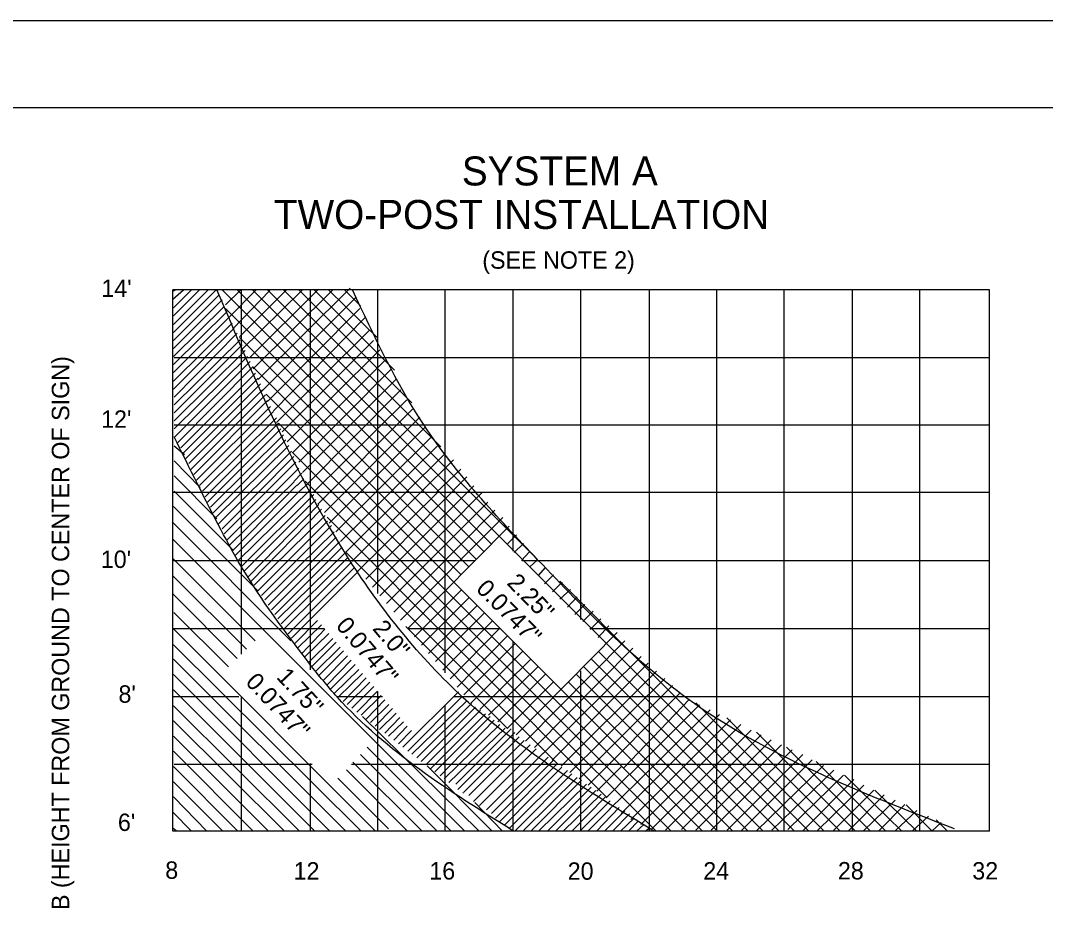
# Model space of a CAD drawing. Extents: x 644358 to 648627, y 294594 to 295782.
# Drawn here: x 645566.7 to 645743.5, y 295627.9 to 295781.6 of the extents above; entities that cross this region are included whole.
import ezdxf

# ---------------------------------------------------------------- set-up
doc = ezdxf.new("R2010")
doc.units = 0
for name, color, linetype in [('1', 7, 'Continuous'), ('10', 7, 'Continuous'), ('2', 7, 'Continuous'), ('4', 7, 'Continuous'), ('PLT-BNDY', 7, 'Continuous')]:
    doc.layers.add(name, color=color, linetype=linetype)

msp = doc.modelspace()

# ---------------------------------------------------------------- linework, layer by layer
at = {"layer": '1'}
msp.add_line((645239.31, 295766.63), (646025.31, 295766.63), dxfattribs=at)
at = {"layer": '10'}
for p, q in [((645606.19, 295723.43), (645618.06, 295735.31)), ((645607.69, 295719.68), (645623.56, 295735.43)), ((645592.94, 295734.93), (645593.44, 295735.18)), ((645592.94, 295733.56), (645594.81, 295735.18)), ((645593.06, 295732.06), (645596.19, 295735.18)), ((645593.06, 295730.68), (645597.56, 295735.18)), ((645593.06, 295729.18), (645599.06, 295735.18)), ((645593.06, 295727.81), (645600.44, 295735.18)), ((645593.06, 295726.43), (645600.94, 295734.31)), ((645646.62, 295690), (645601.44, 295735.18)), ((645602.06, 295732.56), (645604.69, 295735.18)), ((645602.69, 295730.43), (645607.31, 295735.18)), ((645603.31, 295728.43), (645609.69, 295735.06)), ((645647.92, 295691.32), (645604.06, 295735.18)), ((645604.44, 295727.06), (645612.56, 295735.18)), ((645604.69, 295724.68), (645615.31, 295735.18)), ((645650.65, 295691.28), (645606.69, 295735.18)), ((645606.81, 295721.56), (645620.56, 295735.18)), ((645608.19, 295717.56), (645624.44, 295733.81)), ((645655.79, 295688.71), (645609.31, 295735.18)), ((645639.19, 295708.06), (645612.06, 295735.18)), ((645634.19, 295715.68), (645614.69, 295735.18)), ((645631.19, 295721.31), (645617.31, 295735.18)), ((645628.31, 295726.81), (645619.81, 295735.18)), ((645625.31, 295732.43), (645622.56, 295735.18)), ((645593.06, 295725.06), (645601.44, 295733.43)), ((645593.06, 295723.68), (645601.81, 295732.31)), ((645645.31, 295688.68), (645602.06, 295731.93)), ((645609.31, 295715.93), (645625.19, 295731.93)), ((645593.06, 295722.31), (645602.31, 295731.43)), ((645593.06, 295720.93), (645602.81, 295730.56)), ((645610.31, 295714.31), (645626.06, 295730.31)), ((645593.06, 295719.43), (645603.19, 295729.43)), ((645593.06, 295718.06), (645603.56, 295728.56)), ((645593.19, 295716.68), (645604.06, 295727.68)), ((645593.19, 295715.31), (645604.56, 295726.56)), ((645644.01, 295687.37), (645604.44, 295726.93)), ((645610.81, 295712.31), (645626.81, 295728.18)), ((645593.19, 295713.93), (645604.94, 295725.68)), ((645611.81, 295710.68), (645627.56, 295726.43)), ((645612.69, 295708.93), (645628.69, 295724.81)), ((645593.19, 295712.56), (645605.44, 295724.68)), ((645593.19, 295711.18), (645605.81, 295723.68)), ((645613.69, 295707.18), (645629.56, 295723.06)), ((645593.19, 295709.68), (645606.31, 295722.81)), ((645593.81, 295708.81), (645606.69, 295721.81)), ((645642.67, 295686.01), (645606.69, 295721.93)), ((645614.69, 295705.43), (645630.56, 295721.43)), ((645594.31, 295707.93), (645607.19, 295720.81)), ((645594.69, 295706.93), (645607.69, 295719.93)), ((645615.31, 295703.68), (645631.44, 295719.68)), ((645595.19, 295706.06), (645608.06, 295718.93)), ((645595.69, 295705.18), (645608.44, 295717.93)), ((645615.81, 295701.31), (645632.31, 295717.93)), ((645596.06, 295704.18), (645608.94, 295717.06)), ((645596.56, 295703.31), (645609.31, 295716.06)), ((645672.23, 295653.91), (645609.06, 295717.18)), ((645617.19, 295700.18), (645633.31, 295716.18)), ((645597.06, 295702.31), (645609.81, 295715.06)), ((645597.56, 295701.43), (645610.31, 295714.18)), ((645617.94, 295698.18), (645634.31, 295714.56)), ((645598.06, 295700.43), (645610.81, 295713.06)), ((645619.11, 295696.74), (645635.56, 295713.18)), ((645598.56, 295699.43), (645611.19, 295712.18)), ((645598.94, 295698.56), (645611.56, 295711.18)), ((645681.56, 295641.81), (645611.19, 295712.18)), ((645619.94, 295694.94), (645636.44, 295711.43)), ((645599.44, 295697.68), (645612.06, 295710.18)), ((645599.94, 295696.68), (645612.44, 295709.31)), ((645621.07, 295693.44), (645637.56, 295709.81)), ((645594.94, 295706.68), (645593.19, 295708.18)), ((645600.31, 295695.81), (645612.94, 295708.31)), ((645600.81, 295694.81), (645613.44, 295707.31)), ((645678.94, 295641.81), (645613.56, 295707.18)), ((645621.87, 295691.74), (645638.56, 295708.18)), ((645597.69, 295701.06), (645593.19, 295705.68)), ((645601.44, 295693.93), (645613.81, 295706.43)), ((645601.81, 295693.06), (645614.19, 295705.43)), ((645633.14, 295700.18), (645639.69, 295706.68)), ((645635.69, 295700.18), (645641.35, 295705.84)), ((645602.31, 295692.06), (645614.69, 295704.43)), ((645613.81, 295702.1), (645615.19, 295703.56)), ((645638.36, 295700.18), (645642.63, 295704.23)), ((645600.56, 295695.68), (645593.19, 295703.06)), ((645602.81, 295691.18), (645613.87, 295702.02)), ((645614.4, 295701.4), (645615.56, 295702.56)), ((645676.31, 295641.81), (645615.81, 295702.18)), ((645626.23, 295685.23), (645643.69, 295702.88)), ((645603.44, 295690.18), (645593.19, 295700.43)), ((645603.31, 295690.18), (645614.35, 295701.46)), ((645603.69, 295689.31), (645615.03, 295700.65)), ((645604.19, 295688.43), (645616.7, 295700.7)), ((645615.06, 295700.62), (645616.06, 295701.56)), ((645622.81, 295689.93), (645633.14, 295700.18)), ((645623.81, 295688.31), (645635.69, 295700.18)), ((645624.81, 295686.56), (645638.59, 295700.18)), ((645627.38, 295683.87), (645644.88, 295701.38)), ((645628.64, 295682.39), (645646.24, 295700.17)), ((645604.81, 295687.43), (645617.26, 295699.88)), ((645605.31, 295686.68), (645617.64, 295699.01)), ((645629.79, 295681.04), (645647.29, 295698.53)), ((645607.67, 295683.2), (645593.06, 295697.81)), ((645605.94, 295685.68), (645618.16, 295698.15)), ((645606.44, 295684.93), (645618.59, 295697.34)), ((645631.05, 295679.55), (645648.5, 295697.18)), ((645613.33, 295674.62), (645592.84, 295695.12)), ((645606.98, 295684.23), (645619.23, 295696.22)), ((645607.65, 295683.28), (645619.63, 295695.25)), ((645667.75, 295647.63), (645619.57, 295695.93)), ((645632.2, 295678.2), (645649.87, 295695.87)), ((645608.27, 295682.45), (645620.35, 295694.53)), ((645608.82, 295681.69), (645620.79, 295693.4)), ((645633.46, 295676.71), (645650.98, 295694.41)), ((645650.65, 295691.28), (645652.26, 295692.88)), ((645643.22, 295641.88), (645592.91, 295692.19)), ((645609.41, 295680.78), (645621.15, 295692.52)), ((645609.98, 295679.98), (645621.73, 295691.72)), ((645700.19, 295641.81), (645650.65, 295691.28)), ((645651.85, 295689.84), (645653.44, 295691.43)), ((645610.53, 295679.15), (645622.15, 295690.77)), ((645611.06, 295678.43), (645622.59, 295689.71)), ((645659.44, 295653.31), (645622.81, 295689.93)), ((645653.11, 295688.49), (645654.44, 295689.93)), ((645607.18, 295674.62), (645592.91, 295688.9)), ((645611.67, 295677.54), (645623.08, 295688.95)), ((645612.24, 295676.73), (645623.75, 295688.2)), ((645654.54, 295687.39), (645655.81, 295688.56)), ((645605.65, 295673.16), (645592.91, 295685.9)), ((645612.83, 295675.83), (645624.29, 295687.29)), ((645613.43, 295675.06), (645624.95, 295686.55)), ((645656.02, 295685.91), (645657.31, 295687.31)), ((645657.06, 295684.43), (645658.61, 295685.98)), ((645658.44, 295683.06), (645660.1, 295684.73)), ((645702.69, 295641.81), (645659.69, 295684.93)), ((645604.08, 295671.59), (645592.99, 295682.68)), ((645634.67, 295675.29), (645642.78, 295683.41)), ((645659.69, 295681.81), (645661.53, 295683.48)), ((645635.87, 295673.87), (645644.1, 295682.09)), ((645637.08, 295672.45), (645645.45, 295680.74)), ((645661.06, 295680.43), (645662.7, 295682.23)), ((645662.31, 295679.18), (645664, 295680.88)), ((645602.54, 295670.13), (645593.14, 295679.53)), ((645638.28, 295671.03), (645646.72, 295679.47)), ((645663.69, 295677.93), (645665.46, 295679.71)), ((645614.02, 295674.14), (645617.91, 295678.13)), ((645614.54, 295673.41), (645618.58, 295677.35)), ((645650.66, 295659.49), (645633.15, 295677.07)), ((645639.54, 295669.54), (645648.09, 295678.09)), ((645664.94, 295676.56), (645666.8, 295678.42)), ((645666.31, 295675.18), (645668.16, 295677.21)), ((645627.94, 295641.81), (645593.06, 295676.68)), ((645615.24, 295672.49), (645619.18, 295676.64)), ((645615.71, 295671.83), (645619.84, 295675.86)), ((645640.81, 295668.06), (645649.38, 295676.8)), ((645642.01, 295666.64), (645650.69, 295675.49)), ((645652.17, 295658.43), (645669.61, 295676.04)), ((645625.44, 295641.81), (645593.06, 295673.93)), ((645616.38, 295670.88), (645620.54, 295675.04)), ((645616.92, 295670.17), (645621.11, 295674.36)), ((645617.61, 295669.36), (645621.8, 295673.55)), ((645643.16, 295665.28), (645652.03, 295674.15)), ((645653.79, 295657.3), (645670.95, 295674.63)), ((645618.17, 295668.67), (645622.37, 295672.87)), ((645618.91, 295667.78), (645623.07, 295672.05)), ((645644.37, 295663.86), (645653.34, 295672.84)), ((645655.33, 295656.22), (645672.3, 295673.35)), ((645656.82, 295655.18), (645673.75, 295671.93)), ((645697.56, 295641.81), (645666.37, 295672.76)), ((645622.81, 295641.81), (645593.06, 295671.43)), ((645619.55, 295667.04), (645623.7, 295671.31)), ((645620.16, 295666.29), (645624.38, 295670.51)), ((645645.93, 295662.8), (645654.69, 295671.48)), ((645647.4, 295661.77), (645655.98, 295670.19)), ((645658.42, 295654.06), (645674.98, 295670.79)), ((645692.19, 295641.81), (645663.81, 295670.18)), ((645694.81, 295641.81), (645665.12, 295671.5)), ((645620.06, 295641.81), (645593.06, 295668.81)), ((645620.79, 295665.54), (645625.06, 295669.7)), ((645621.56, 295664.93), (645625.69, 295668.96)), ((645622.31, 295664.18), (645626.33, 295668.21)), ((645649.02, 295660.64), (645657.27, 295668.89)), ((645659.97, 295652.97), (645676.41, 295669.41)), ((645661.43, 295651.92), (645677.82, 295668.13)), ((645689.56, 295641.81), (645662.51, 295668.86)), ((645623.01, 295663.63), (645626.96, 295667.48)), ((645623.86, 295662.98), (645627.6, 295666.72)), ((645650.63, 295659.51), (645658.58, 295667.46)), ((645686.94, 295641.81), (645661.18, 295667.53)), ((645663.04, 295650.79), (645679.15, 295666.9)), ((645617.44, 295641.81), (645593.06, 295666.18)), ((645624.71, 295662.34), (645628.24, 295665.96)), ((645625.43, 295661.78), (645628.91, 295665.18)), ((645632.64, 295656.26), (645642.22, 295665.84)), ((645633.49, 295655.61), (645642.78, 295664.9)), ((645664.59, 295649.71), (645680.5, 295665.62)), ((645614.81, 295641.81), (645593.06, 295663.43)), ((645626.32, 295661.1), (645629.52, 295664.46)), ((645627.06, 295660.53), (645630.22, 295663.63)), ((645627.88, 295659.9), (645630.83, 295662.92)), ((645634.21, 295655.05), (645643.62, 295664.21)), ((645635.04, 295654.42), (645644.45, 295663.83)), ((645635.82, 295653.82), (645645.18, 295663.18)), ((645670.72, 295652.65), (645682.06, 295664.56)), ((645671.81, 295651.56), (645683.83, 295663.57)), ((645705.31, 295641.81), (645683.19, 295663.93)), ((645645.81, 295641.81), (645625.69, 295661.59)), ((645628.62, 295659.34), (645631.49, 295662.14)), ((645629.5, 295658.67), (645632.11, 295661.41)), ((645636.6, 295653.22), (645646.05, 295662.68)), ((645637.45, 295652.57), (645646.88, 295662)), ((645638.16, 295652.03), (645647.69, 295661.56)), ((645673.09, 295650.28), (645685.66, 295662.7)), ((645674.42, 295648.95), (645687.28, 295661.91)), ((645708.06, 295641.81), (645688.55, 295661.32)), ((645612.19, 295641.81), (645593.06, 295660.81)), ((645630.17, 295658.15), (645632.75, 295660.65)), ((645631.05, 295657.48), (645633.37, 295659.92)), ((645639.06, 295651.34), (645648.37, 295660.93)), ((645639.74, 295650.82), (645649.36, 295660.16)), ((645640.59, 295650.17), (645650.26, 295659.55)), ((645641.77, 295649.88), (645651.32, 295659.42)), ((645671.94, 295643.81), (645689.13, 295661)), ((645673.69, 295642.93), (645690.94, 295660.18)), ((645609.44, 295641.81), (645593.06, 295658.18)), ((645631.86, 295656.86), (645634.15, 295659.15)), ((645642.41, 295649.24), (645651.95, 295658.78)), ((645643.14, 295648.51), (645652.68, 295658.05)), ((645675.56, 295642.18), (645692.74, 295659.22)), ((645677.94, 295641.93), (645694.43, 295658.43)), ((645680.69, 295642.06), (645696.17, 295657.55)), ((645710.69, 295641.81), (645693.62, 295658.88)), ((645640.86, 295641.88), (645626.46, 295656.29)), ((645644.04, 295647.92), (645653.56, 295657.43)), ((645644.82, 295646.89), (645654.58, 295656.65)), ((645645.85, 295646.21), (645655.62, 295655.98)), ((645683.19, 295641.93), (645697.95, 295656.7)), ((645685.81, 295641.93), (645699.82, 295655.8)), ((645713.31, 295641.81), (645698.82, 295656.3)), ((645606.81, 295641.81), (645593.06, 295655.56)), ((645638.41, 295641.88), (645625.31, 295654.99)), ((645647.05, 295645.48), (645656.82, 295655.25)), ((645647.93, 295644.81), (645657.7, 295654.57)), ((645684.31, 295641.81), (645671.85, 295654.3)), ((645688.56, 295641.93), (645701.62, 295654.99)), ((645690.94, 295641.81), (645703.24, 295654.11)), ((645604.19, 295641.81), (645593.06, 295652.93)), ((645633.46, 295641.81), (645622.91, 295652.36)), ((645635.94, 295641.81), (645624.03, 295653.71)), ((645648.06, 295641.81), (645636.8, 295653.07)), ((645648.63, 295644.01), (645658.58, 295653.95)), ((645649.34, 295643.46), (645659.33, 295653.46)), ((645650.19, 295642.81), (645660.06, 295652.82)), ((645650.94, 295642.18), (645661.03, 295652.27)), ((645666.07, 295648.68), (645670.4, 295652.97)), ((645693.56, 295641.81), (645705.19, 295653.14)), ((645696.31, 295641.93), (645707, 295652.32)), ((645715.94, 295641.81), (645703.96, 295653.79)), ((645630.17, 295642.18), (645621.41, 295650.94)), ((645651.94, 295641.81), (645661.8, 295651.67)), ((645653.31, 295641.81), (645662.7, 295651.06)), ((645654.69, 295641.81), (645663.45, 295650.57)), ((645667.68, 295647.55), (645671.75, 295651.62)), ((645699.06, 295642.06), (645708.62, 295651.47)), ((645701.56, 295641.81), (645710.44, 295650.68)), ((645718.69, 295641.81), (645708.82, 295651.45)), ((645601.56, 295641.81), (645593.06, 295650.31)), ((645642.14, 295648.98), (645642.43, 295649.25)), ((645656.06, 295641.81), (645664.31, 295649.91)), ((645657.56, 295641.81), (645665.1, 295649.35)), ((645658.94, 295641.81), (645665.94, 295648.82)), ((645668.31, 295645.56), (645673.09, 295650.28)), ((645670.31, 295644.81), (645674.42, 295648.95)), ((645704.06, 295641.81), (645712.15, 295649.74)), ((645706.81, 295641.81), (645713.87, 295648.87)), ((645721.31, 295641.81), (645714.05, 295648.84)), ((645598.81, 295641.81), (645593.06, 295647.68)), ((645642.97, 295648.34), (645643.09, 295648.47)), ((645660.31, 295641.81), (645666.82, 295648.16)), ((645661.81, 295641.81), (645667.51, 295647.65)), ((645663.19, 295641.81), (645668.38, 295647)), ((645709.44, 295641.81), (645715.69, 295648.06)), ((645712.06, 295641.81), (645717.57, 295647.15)), ((645649.83, 295641.81), (645645.08, 295646.73)), ((645664.56, 295641.81), (645668.44, 295645.68)), ((645666.06, 295641.81), (645669.96, 295645.86)), ((645667.44, 295641.81), (645670.9, 295645.27)), ((645714.72, 295641.84), (645719.25, 295646.37)), ((645717.57, 295641.83), (645721.27, 295645.35)), ((645719.44, 295646.31), (645723.94, 295641.81)), ((645596.19, 295641.81), (645592.94, 295645.06)), ((645668.81, 295641.81), (645671.75, 295644.75)), ((645670.19, 295641.81), (645672.56, 295644.04)), ((645671.56, 295641.81), (645673.31, 295643.56)), ((645720.57, 295641.83), (645723.32, 295644.4)), ((645726.56, 295641.81), (645724.64, 295643.73)), ((645593.56, 295641.81), (645592.94, 295642.31)), ((645672.94, 295641.81), (645674.22, 295642.93)), ((645674.44, 295641.81), (645675.16, 295642.35)), ((645675.81, 295641.81), (645675.81, 295641.81)), ((645723.9, 295641.81), (645725.5, 295643.3))]:
    msp.add_line(p, q, dxfattribs=at)
at = {"layer": '2'}
for p, q in [((645733.81, 295735.18), (645592.94, 295735.18)), ((645592.94, 295688.43), (645592.94, 295735.18)), ((645604.81, 295672.31), (645604.81, 295735.18)), ((645616.69, 295688.43), (645616.69, 295735.18)), ((645628.31, 295682.77), (645628.31, 295735.18)), ((645639.94, 295700.18), (645639.94, 295735.18)), ((645651.69, 295690.07), (645651.69, 295735.18)), ((645663.31, 295678.29), (645663.31, 295735.18)), ((645675.19, 295641.81), (645675.19, 295735.18)), ((645686.81, 295641.81), (645686.81, 295735.18)), ((645698.44, 295641.81), (645698.44, 295735.18)), ((645710.19, 295641.81), (645710.19, 295735.18)), ((645721.81, 295641.81), (645721.81, 295735.18)), ((645733.81, 295641.81), (645733.81, 295735.18)), ((645733.69, 295723.43), (645593.19, 295723.43)), ((645733.69, 295711.81), (645593.19, 295711.81)), ((645644.31, 295700.18), (645592.94, 295700.18)), ((645639.94, 295669.08), (645639.94, 295700.18)), ((645733.69, 295700.18), (645641.73, 295700.18)), ((645592.94, 295641.81), (645592.94, 295688.43)), ((645616.69, 295688.43), (645592.94, 295688.43)), ((645616.69, 295669.63), (645616.69, 295688.43)), ((645645.07, 295688.43), (645616.69, 295688.43)), ((645733.69, 295688.43), (645653.21, 295688.43)), ((645619.14, 295676.68), (645593.04, 295676.68)), ((645649.49, 295676.68), (645633.48, 295676.68)), ((645733.69, 295676.68), (645664.87, 295676.68)), ((645651.69, 295653.31), (645651.69, 295674.49)), ((645663.31, 295641.81), (645663.31, 295669.47)), ((645604.35, 295664.93), (645592.94, 295664.93)), ((645604.81, 295641.81), (645604.81, 295664.82)), ((645629.11, 295664.93), (645621.32, 295664.93)), ((645628.31, 295641.81), (645628.31, 295665.88)), ((645675.08, 295664.93), (645641.36, 295664.93)), ((645733.69, 295664.93), (645675.08, 295664.93)), ((645639.94, 295641.81), (645639.94, 295663.47)), ((645617, 295653.31), (645593.19, 295653.31)), ((645733.78, 295653.31), (645623.75, 295653.31)), ((645651.69, 295641.81), (645651.69, 295653.31)), ((645639.94, 295641.81), (645592.94, 295641.81)), ((645733.81, 295641.81), (645639.94, 295641.81))]:
    msp.add_line(p, q, dxfattribs=at)
at = {"layer": '4'}
for p, q in [((645600.94, 295735.18), (645600.94, 295735.18)), ((645623.94, 295735.18), (645623.94, 295735.18)), ((645610.81, 295711.81), (645610.81, 295711.81)), ((645636.31, 295711.81), (645636.31, 295711.81)), ((645623.44, 295688.56), (645623.44, 295688.56)), ((645655.94, 295688.56), (645655.94, 295688.56)), ((645643.06, 295664.81), (645643.06, 295664.81)), ((645681.69, 295664.68), (645681.69, 295664.68)), ((645616.69, 295641.81), (645616.69, 295653.45)), ((645676.06, 295641.81), (645676.06, 295641.81)), ((645728.19, 295641.81), (645728.19, 295641.81))]:
    msp.add_line(p, q, dxfattribs=at)
for points in [[(645675.94, 295641.81), (645643.06, 295664.81), (645623.44, 295688.56), (645610.81, 295711.81), (645600.56, 295735.18)], [(645727.81, 295642.18), (645681.69, 295664.68), (645655.94, 295688.56), (645636.31, 295711.81), (645623.94, 295735.18)], [(645616.6, 295670.57), (645604.69, 295687.56), (645601.31, 295693.68), (645593.19, 295709.81)], [(645651.69, 295641.81), (645621.31, 295664.93), (645616.6, 295670.57)]]:
    msp.add_spline(points, degree=3, dxfattribs=at)
at = {"layer": 'PLT-BNDY'}
msp.add_lwpolyline([(645199.31, 295781.63), (646040.31, 295781.63), (646040.31, 295187.63), (645199.31, 295187.63)], close=True, dxfattribs=at)

# ---------------------------------------------------------------- texts
at = {"layer": '4'}
for s, height, p in [('SYSTEM A', 5, (645642.81, 295753.17)), ('TWO-POST INSTALLATION', 5, (645610.39, 295745.67)), ('(SEE NOTE 2)', 3, (645646.34, 295738.81)), ("14'", 3, (645580.62, 295733.93)), ("12'", 3, (645580.58, 295711.37)), ("10'", 3, (645580.53, 295687.19)), ("8'", 3, (645583.58, 295663.94)), ("6'", 3, (645583.48, 295641.82)), ('8', 3, (645591.65, 295633.57)), ('12', 3, (645613.79, 295633.44)), ('16', 3, (645637.2, 295633.44)), ('20', 3, (645661.07, 295633.4)), ('24', 3, (645684.46, 295633.44)), ('28', 3, (645707.68, 295633.46)), ('32', 3, (645730.86, 295633.45))]:
    msp.add_text(s, height=height, dxfattribs=at).set_placement(p)
for s, height, rotation, p in [(' B (HEIGHT FROM GROUND TO CENTER OF SIGN)', 3.005, 90, (645575.08, 295627.06)), ('2.25"', 3, 314.6785, (645650.41, 295684.45)), ('0.0747"', 3, 314.6785, (645645.1, 295683.42)), ('0.0747"', 3, 310.3915, (645620.94, 295677.16)), ('2.0"', 3, 310.3915, (645627.28, 295676.65)), ('0.0747"', 3, 313.1129, (645605.34, 295667.38)), ('1.75"', 3, 313.1129, (645610.68, 295668.26))]:
    msp.add_text(s, height=height, rotation=rotation, dxfattribs=at).set_placement(p)

doc.saveas('drawing.dxf')
